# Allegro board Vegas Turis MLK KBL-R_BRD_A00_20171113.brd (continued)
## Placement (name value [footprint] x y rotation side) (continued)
C6317  SC4D7U6D3V3KX-GP  [C603H36]  185.18 65.13 270 bottom
C6318  SC1U10V2KX-1GP  [C402H22]  173.72 57.25 270 top
C6319  SCD1U16V2KX-3GP  [C402H22]  173.81 56.18 270 top
C6320  SC1U10V2KX-1GP  [C402H22]  170.92 70.66 0 bottom
C6401  SCD1U16V2KX-3GP  [C402H22]  195.96 174.23 0 bottom
C6503  SCD1U16V2KX-3GP  [C402H22]  141.15 24.33 270 bottom
C6504  SCD1U16V2KX-3GP  [C402H22]  148.23 17.3 270 bottom
C6701  SCD1U16V2KX-3GP  [C402H22]  180.91 48.43 90 bottom
C6702  SCD1U16V2KX-3GP  [C402H22]  182.55 47.34 270 bottom
C6703  SC10U6D3V3MX-GP  [C603H38]  182.24 52.68 90 bottom
C7601  SCD22U10V2KX-L1-GP  [C402H22]  145.24 132.3 270 top
C7602  SCD22U10V2KX-L1-GP  [C402H22]  145.24 131.41 270 top
C7603  SCD22U10V2KX-L1-GP  [C402H22]  145.24 134.52 270 top
C7604  SCD22U10V2KX-L1-GP  [C402H22]  145.24 133.63 270 top
C7605  SCD22U10V2KX-L1-GP  [C402H22]  143.46 135.91 270 top
C7606  SCD22U10V2KX-L1-GP  [C402H22]  143.46 135.03 270 top
C7607  SCD22U10V2KX-L1-GP  [C402H22]  145.24 136.3 270 top
C7608  SCD22U10V2KX-L1-GP  [C402H22]  145.24 137.18 270 top
C7609  SC47P50V2JN-3GP  [C402H22]  145.9 123.56 0 top
C7710  SCD1U16V2KX-3GP  [C402H22]  156.63 122.39 270 top
C7711  SC1U10V2KX-1GP  [C402H22]  156.63 121.56 270 top
C7713  SC10U6D3V3MX-GP  [C603H38]  156.55 123.95 180 top
C7714  SCD1U16V2KX-3GP  [C402H22]  171.19 125.25 270 top
C7715  SC1U10V2KX-1GP  [C402H22]  171.19 126.14 270 top
C7801  SC1U10V2KX-1GP  [C402H22]  158.19 139.01 270 top
C7802  SC100P50V2JN-3GP  [C402H22]  168.05 171.35 180 bottom
C7803  SC68P50V2JN-1GP  [C402H22]  169.39 172.85 90 bottom
C7805  SC1U10V2KX-1GP  [C402H22]  159.9 139.01 270 top
C7821  SCD1U16V2KX-3GP  [C402H22]  184.3 139.36 180 top
C7822  SCD1U16V2KX-3GP  [C402H22]  179.66 139.64 180 top
C7901  SC6D8P50V2CN-DL-GP  [C402H22]  154.28 123.15 0 bottom
C7903  SC6D8P50V2CN-DL-GP  [C402H22]  154.37 121.46 180 bottom
C7904  SC1U10V2KX-1GP  [C402H22]  169.53 134.61 90 top
C7918  SCD082U16V2KX-GP  [C402H22]  149.26 123.83 180 top
C7919  SCD68U16V3KX-GP-U  [C603H36]  149.12 121.79 270 top
C7920  SCD68U16V3KX-GP-U  [C603H36]  179.3 135.42 0 top
C7921  SCD01U50V2KX-L-GP  [C402H22]  167.52 127.4 0 top
C8001  SC10U6D3V3MX-GP  [C603H38]  194.78 136.24 90 top
C8002  SC10U6D3V3MX-GP  [C603H38]  149.42 125.31 270 top
C8003  SC1U10V2KX-1GP  [C402H22]  166.98 146.83 270 top
C8004  SC1U10V2KX-1GP  [C402H22]  171.38 146.92 90 top
C8005  SC1U10V2KX-1GP  [C402H22]  149.18 150.24 0 top
C8006  SC1U10V2KX-1GP  [C402H22]  173.43 146.9 270 top
C8007  SCD1U16V2KX-3GP  [C402H22]  150.93 150.24 0 top
C8008  SC1U10V2KX-1GP  [C402H22]  170.42 126.99 90 top
C8009  SC1U10V2KX-1GP  [C402H22]  176.88 166.76 180 top
C8010  SC10U6D3V3MX-GP  [C603H38]  167.42 138.63 90 top
C8011  SCD1U16V2KX-3GP  [C402H22]  167.37 137.59 90 top
C8012  SCD1U16V2KX-3GP  [C402H22]  170.68 122.59 0 top
C8013  SC1U10V2KX-1GP  [C402H22]  167.65 139.68 90 top
C8014  SCD01U50V2KX-L-GP  [C402H22]  194.47 138.37 90 top
C8015  SC1U10V2KX-1GP  [C402H22]  163.56 138.3 270 top
C8016  SC10U6D3V3MX-GP  [C603H38]  165.05 137.82 0 top
C8017  SC1U10V2KX-1GP  [C402H22]  170.42 127.83 90 top
C8018  SC1U10V2KX-1GP  [C402H22]  173.61 139.23 0 top
C8019  SC1U10V2KX-1GP  [C402H22]  174.25 122.62 180 bottom
C8020  SC1U10V2KX-1GP  [C402H22]  187.04 123.38 0 bottom
C8021  SC1U10V2KX-1GP  [C402H22]  169.51 139.17 270 top
C8022  SC1U10V2KX-1GP  [C402H22]  169.51 139.99 270 top
C8023  SC1U10V2KX-1GP  [C402H22]  168.22 125.55 90 top
C8024  SC1U10V2KX-1GP  [C402H22]  170.79 135.18 180 top
C8025  SC1U10V2KX-1GP  [C402H22]  168.22 124.74 90 top
C8026  SC1U10V2KX-1GP  [C402H22]  184.68 126.13 90 top
C8027  SC1U10V2KX-1GP  [C402H22]  183 126.13 270 top
C8028  SC1U10V2KX-1GP  [C402H22]  174.23 134.81 90 top
C8029  SC1U10V2KX-1GP  [C402H22]  175.32 137.46 270 top
C8030  SC1U10V2KX-1GP  [C402H22]  177.21 137.85 90 top
C8031  SC1U10V2KX-1GP  [C402H22]  181.28 161.62 180 top
C8032  SC1U10V2KX-1GP  [C402H22]  178.27 147.56 180 top
C8033  SC1U10V2KX-1GP  [C402H22]  179.51 158.91 180 top
C8034  SC1U10V2KX-1GP  [C402H22]  175.35 160.16 180 top
C8035  SC1U10V2KX-1GP  [C402H22]  171.16 138.34 180 top
C8036  SC1U10V2KX-1GP  [C402H22]  175.11 138.7 90 top
C8037  SC1U10V2KX-1GP  [C402H22]  175.37 139.99 90 top
C8038  SC10U6D3V3MX-GP  [C603H38]  168.18 122.37 90 top
C8039  SC10U6D3V3MX-GP  [C603H38]  168.18 121.1 90 top
C8040  SC10U6D3V3MX-GP  [C603H38]  162.86 120.48 90 bottom
C8041  SC10U6D3V3MX-GP  [C603H38]  162.86 123.02 90 bottom
C8042  SC1U10V2KX-1GP  [C402H22]  194.47 137.48 90 top
C8043  SC10U6D3V3MX-GP  [C603H38]  194.66 138.81 270 bottom
C8044  SC10U6D3V3MX-GP  [C603H38]  194.66 137.53 270 bottom
C8045  SC1U10V2KX-1GP  [C402H22]  194.24 136.47 270 bottom
C8046  SCD1U16V2KX-3GP  [C402H22]  169.44 138.35 270 top
C8047  SCD1U16V2KX-3GP  [C402H22]  168.67 136.27 180 top
C8048  SC1U10V2KX-1GP  [C402H22]  167.84 136.34 180 top
C8049  SC1U10V2KX-1GP  [C402H22]  167.01 136.34 180 top
C8050  SC1U10V2KX-1GP  [C402H22]  169.49 136.27 180 top
C8051  SC4D7U6D3V3KX-GP  [C603H36]  162.86 121.75 90 bottom
C8052  SC4D7U6D3V3KX-GP  [C603H36]  168.23 121.82 270 bottom
C8053  SC10U6D3V3MX-GP  [C603H38]  188.83 136.93 270 bottom
C8054  SC1U10V2KX-1GP  [C402H22]  194.67 140.83 90 top
C8055  SC1U10V2KX-1GP  [C402H22]  185.53 137.16 180 bottom
C8056  SCD1U16V2KX-3GP  [C402H22]  186.3 137.16 180 bottom
C8057  SC1U10V2KX-1GP  [C402H22]  163.61 139.95 270 top
C8058  SC1U10V2KX-1GP  [C402H22]  175.32 136.65 270 top
C8059  SC1U10V2KX-1GP  [C402H22]  177.61 136.97 90 top
C8060  SC1U10V2KX-1GP  [C402H22]  172.79 138.33 180 top
C8061  SC1U10V2KX-1GP  [C402H22]  169.51 137.52 270 top
C8062  SC1U10V2KX-1GP  [C402H22]  171.97 138.33 180 top
C8063  SC10U6D3V3MX-GP  [C603H38]  172.8 136.37 270 top
C8064  SC10U6D3V3MX-GP  [C603H38]  168.23 123.09 270 bottom
C8065  SC1U10V2KX-1GP  [C402H22]  163.61 139.13 270 top
C8066  SC22U6D3V3MX-1-GP  [C603H40]  179.66 125.27 180 top
C8101  SC1U10V2KX-1GP  [C402H22]  150.06 166.52 0 top
C8102  SC1U10V2KX-1GP  [C402H22]  188.77 167.27 180 bottom
C8103  SC1U10V2KX-1GP  [C402H22]  150.5 165.13 270 top
C8104  SC1U10V2KX-1GP  [C402H22]  189.32 164.74 180 bottom
C8105  SCD1U16V2KX-3GP  [C402H22]  163.95 161.25 0 top
C8106  SCD1U16V2KX-3GP  [C402H22]  187.74 174.25 0 bottom
C8107  SCD1U16V2KX-3GP  [C402H22]  189.01 170.12 0 bottom
C8108  SCD1U16V2KX-3GP  [C402H22]  186.12 174.26 0 bottom
C8109  SCD1U16V2KX-3GP  [C402H22]  161.03 160.2 90 top
C8110  SCD1U16V2KX-3GP  [C402H22]  153.42 158.22 180 top
C8111  SCD1U16V2KX-3GP  [C402H22]  158.63 162.49 90 top
C8112  SCD1U16V2KX-3GP  [C402H22]  162.54 158.33 180 top
C8113  SC1U10V2KX-1GP  [C402H22]  158.01 174.76 0 bottom
C8114  SC1U10V2KX-1GP  [C402H22]  158.79 174.76 0 bottom
C8115  SC1U10V2KX-1GP  [C402H22]  159.59 174.76 0 bottom
C8116  SC1U10V2KX-1GP  [C402H22]  160.38 174.78 0 bottom
C8117  SC1U10V2KX-1GP  [C402H22]  157.23 174.77 0 bottom
C8118  SC1U10V2KX-1GP  [C402H22]  173.93 174.63 0 bottom
C8119  SC1U10V2KX-1GP  [C402H22]  175.25 174.63 0 bottom
C8120  SC1U10V2KX-1GP  [C402H22]  186.93 174.27 0 bottom
C8121  SC10U6D3V3MX-GP  [C603H38]  179.3 174.66 0 bottom
C8122  SC10U6D3V3MX-GP  [C603H38]  177.07 174.7 0 bottom
C8123  SC1U10V2KX-1GP  [C402H22]  182.96 174.24 0 bottom
C8124  SC1U10V2KX-1GP  [C402H22]  157.58 173.57 180 top
C8125  SC1U10V2KX-1GP  [C402H22]  184.54 174.24 0 bottom
C8126  SC1U10V2KX-1GP  [C402H22]  158.88 173.57 180 top
C8127  SC1U10V2KX-1GP  [C402H22]  160.17 173.57 180 top
C8128  SC1U10V2KX-1GP  [C402H22]  164.12 173.48 180 top
C8129  SC1U10V2KX-1GP  [C402H22]  168.69 173.43 180 top
C8130  SC1U10V2KX-1GP  [C402H22]  190.19 170.31 90 top
C8131  SC10U6D3V3MX-GP  [C603H38]  147.82 156.89 270 top
C8132  SC10U6D3V3MX-GP  [C603H38]  189.92 171.9 90 top
C9106  SC4D7U6D3V3KX-GP  [C603H36]  161.44 60.12 90 bottom
C9107  SCD1U16V2KX-3GP  [C402H22]  153.81 52.85 180 bottom
C9108  SCD1U16V2KX-3GP  [C402H22]  161.53 61.19 90 bottom
C9109  SC4D7U6D3V3KX-GP  [C603H36]  160.77 56.11 270 bottom
C9111  SCD1U16V2KX-3GP  [C402H22]  154.62 52.85 180 bottom
C9112  SCD1U16V2KX-3GP  [C402H22]  160.83 55.05 270 bottom
C9113  SC4D7U6D3V3KX-GP  [C603H36]  150.03 60.55 90 bottom
C9114  SC2200P50V2KX-2GP  [C402H22]  157.65 50.7 270 bottom
C9115  SC2200P50V2KX-2GP  [C402H22]  157.6 51.51 270 bottom
C9116  SCD1U16V2KX-3GP  [C402H22]  157.64 49.92 270 bottom
C9201  SCD1U16V2KX-3GP  [C402H22]  189.04 55.13 90 bottom
C9202  SC1U10V2KX-1GP  [C402H22]  189.04 55.97 90 bottom
CPU1  SKYLAKE-U-GP  [BGA1356M4224-U2H52]  119.5 86.3 0 bottom
D1702  RB751V-40H-GP  [SOD323AKH38]  154.29 62.03 270 top
D2101  BAT54A-11-GP  [SOT-23-9H44]  139.78 43.6 270 bottom
D2102  RB751VM-40TE-17-GP  [SOD323-2513AKH36]  177.71 26.13 270 bottom
D2402  RB751V-40H-GP  [SOD323AKH38]  176.17 45.3 180 bottom
D2403  RB751V-40H-GP  [SOD323AKH38]  176.53 47.91 270 bottom
D2405  RB751V-40H-GP  [SOD323AKH38]  161.02 28.02 0 bottom
D2501  BAT54C-12-GP  [SOT-23-9H44]  38.52 36.54 180 top
D2601  RB551V30-GP  [SOD323AKH38]  108.05 135.91 180 top
D2703  BAT54C-12-GP  [SOT-23-9H44]  173.26 29.49 180 bottom
D2901  BAT54A-11-GP  [SOT-23-9H44]  174.49 13.61 270 bottom
D4001  LBAS16LT1G-GP  [SOT23-2D4-312H44]  66.17 82.45 270 top
D4002  LBAS16LT1G-GP  [SOT23-2D4-312H44]  162.07 80.5 90 bottom
D4304  LBAV99LT1G-1-GP  [SOT23-2D4-312H44]  159.04 181.81 90 top
D4305  LBAV99LT1G-1-GP  [SOT23-2D4-312H44]  161.02 178.23 90 top
D4306  LBAV99LT1G-1-GP  [SOT23-2D4-312H44]  157.82 178.3 90 top
D5502  BAT54C-12-GP  [SOT-23-9H44]  102.46 182 90 top
D5503  BAT54C-12-GP  [SOT-23-9H44]  103.11 176.76 0 top
D5604  RB551V30-GP  [SOD323AKH38]  16.85 81.94 180 top
D5701  LBAW56LT1G-GP  [SOT23-2D4-312H44]  25.61 58.85 0 top
D7601  BAW56-5-GP  [SOT-23-9H44]  146.1 127.87 90 top
D8601  BAT54C-12-GP  [SOT-23-9H44]  140.34 149.91 90 top
D8602  BAT54C-12-GP  [SOT-23-9H44]  190.29 180.48 270 top
DB3  ACES-CON6-58-GP  [50696-00601-001]  156.4 2.3 0 top
DBG1  DM-ACES-CON14-5-GP-01  [DM-87212-1400N-01]  191.45 10.95 270 top
DCIN1  ACES-CON6-63-GP  [50458-00601-W01]  73.4 182.3 180 top
DM1  DDR4-260P-65-GP  [ADDR0206-P013A]  99.4 36.6 0 bottom
DM2  DDR4-260P-64-GP  [ADDR0205-P012A]  91.4 23.4 180 bottom
EC401  SC1KP50V2KX-L-1-GP  [C402H22]  106.71 101.16 0 bottom
EC1702  SC1KP50V2KX-L-1-GP  [C402H22]  144.21 105.54 0 bottom
EC1703  SC1KP50V2KX-L-1-GP  [C402H22]  157.9 76.53 270 bottom
EC1705  SC1KP50V2KX-L-1-GP  [C402H22]  162.86 65.24 0 top
EC1706  SC1KP50V2KX-L-1-GP  [C402H22]  145 105.52 0 bottom
EC1707  SCD1U16V2KX-3GP  [C402H22]  154.31 63.71 270 top
EC1708  SCD01U50V2KX-L-GP  [C402H22]  79.25 83.99 0 top
EC1709  SCD1U16V2KX-3GP  [C402H22]  78.44 89.62 180 top
EC1712  SCD1U16V2KX-3GP  [C402H22]  153.23 67.56 270 bottom
EC1802  SC10P50V2JN-L1-GP  [C402H22]  139.03 62.65 180 bottom
EC1805  SCD1U16V2KX-3GP  [C402H22]  140.02 93.8 180 top
EC1806  SCD1U16V2KX-3GP  [C402H22]  165.29 77.68 90 top
EC1807  SCD1U16V2KX-3GP  [C402H22]  164.1 78.58 270 top
EC1808  SCD1U16V2KX-3GP  [C402H22]  165.04 71.89 90 top
EC1901  SC10P50V2JN-L1-GP  [C402H22]  140.45 52.5 90 bottom
EC1903  SC1KP50V2KX-L-1-GP  [C402H22]  156.63 111.84 90 top
EC2002  SC1KP50V2KX-L-1-GP  [C402H22]  149.6 90.37 180 bottom
EC2101  SCD1U25V2KX-GP  [C402H22]  123.83 87.25 270 top
EC2601  SCD1U16V2KX-3GP  [C402H22]  109.48 135.91 0 top
EC2602  SC10P50V2JN-L1-GP  [C402H22]  108.89 141.02 90 top
EC2701  SCD1U25V2KX-GP  [C402H22]  181.2 12.99 0 top
EC2702  SCD1U25V2KX-GP  [C402H22]  164.34 16.82 270 top
EC2703  SCD1U25V2KX-GP  [C402H22]  184.6 15.2 90 top
EC2704  SCD1U25V2KX-GP  [C402H22]  182.35 12.96 0 top
EC2705  SCD1U25V2KX-GP  [C402H22]  164.17 15.27 270 top
EC2709  SC22P50V2JN-4GP  [C402H22]  169.47 26.92 0 bottom
EC2710  SC22P50V2JN-4GP  [C402H22]  171.12 26.7 0 bottom
EC2711  SC22P50V2JN-4GP  [C402H22]  167.91 26.93 0 bottom
EC2901  SC1KP50V2KX-L-1-GP  [C402H22]  153.59 16.66 270 top
EC2902  SC1KP50V2KX-L-1-GP  [C402H22]  155.28 17.1 270 top
EC2903  SC1KP50V2KX-L-1-GP  [C402H22]  156.98 17.1 270 top
EC2904  SC1KP50V2KX-L-1-GP  [C402H22]  158.68 17.1 270 top
EC2905  SC100P50V2JN-3GP  [C402H22]  180.45 17.93 270 top
EC2906  SC100P50V2JN-3GP  [C402H22]  180.47 18.71 270 top
EC2907  SC100P50V2JN-3GP  [C402H22]  184.53 18.39 180 top
EC2908  SC100P50V2JN-3GP  [C402H22]  183.19 20.75 180 top
EC4301  SC10U25V5KX-L-GP  [C805H56]  76.6 175.09 90 top
EC4302  SCD1U25V2KX-GP  [C402H22]  76.6 173.69 90 top
EC4306  SC10P50V2JN-L1-GP  [C402H22]  148.48 180.21 0 top
EC4307  SCD1U25V2KX-GP  [C402H22]  158.45 177.14 180 bottom
EC4308  SCD1U50V3KX-GP  [C603H36]  157.26 176.79 180 bottom
EC4309  SC10P50V2JN-L1-GP  [C402H22]  153.52 177.78 0 top
EC4310  SC10P50V2JN-L1-GP  [C402H22]  153.49 179.77 180 top
EC5501  SC22P50V2JN-4GP  [C402H22]  105.59 169.92 90 top
EC5502  SC22P50V2JN-4GP  [C402H22]  103.89 169.93 270 top
EC5503  SC33P50V2JN-3GP  [C402H22]  111.34 176.92 90 top
EC5504  SC22P50V2JN-4GP  [C402H22]  106.21 177.05 0 top
EC6401  SCD1U16V2KX-3GP  [C402H22]  186.14 181.61 180 top
EC6402  SCD1U25V2KX-GP  [C402H22]  189.5 13.44 0 bottom
EC6403  SC1KP50V2KX-L-1-GP  [C402H22]  184.92 179.94 270 top
EC6404  SCD1U25V2KX-GP  [C402H22]  170.69 3.46 270 bottom
EC6501  SC33P50V2JN-3GP  [C402H22]  151.38 18.14 270 bottom
EC6502  SC33P50V2JN-3GP  [C402H22]  151.98 22.31 180 top
EC6503  SC33P50V2JN-3GP  [C402H22]  149.69 18.14 90 bottom
EC6504  SC33P50V2JN-3GP  [C402H22]  152.01 20.79 0 top
EC6505  SC33P50V2JN-3GP  [C402H22]  146.42 25.17 270 bottom
EC6506  SC33P50V2JN-3GP  [C402H22]  144.72 25.17 90 bottom
EC8901  SCD1U25V2KX-GP  [C402H22]  109.23 37.19 0 top
EC8902  SCD1U25V2KX-GP  [C402H22]  122.98 78.86 180 top
EC8903  SCD1U25V2KX-GP  [C402H22]  100.13 43.08 180 top
EC8904  SCD1U25V2KX-GP  [C402H22]  112.86 79.22 0 top
EC8905  SCD1U25V2KX-GP  [C402H22]  39.37 17.8 270 bottom
EC8906  SCD1U25V2KX-GP  [C402H22]  42.28 15.62 0 bottom
EC8907  SCD1U25V2KX-GP  [C402H22]  36.25 14.79 90 bottom
EC8908  SCD1U25V2KX-GP  [C402H22]  127.31 81.46 180 top
EC8909  SCD1U25V2KX-GP  [C402H22]  37.32 29.97 90 top
EC8910  SCD1U25V2KX-GP  [C402H22]  83.28 72.82 270 bottom
EC8911  SCD1U25V2KX-GP  [C402H22]  79.92 72.67 0 top
EC8912  SCD1U25V2KX-GP  [C402H22]  93.3 43.39 180 top
EC8913  SCD1U25V2KX-GP  [C402H22]  90.3 17.1 90 top
EC8914  SCD1U25V2KX-GP  [C402H22]  102.57 40.57 180 top
EC8915  SCD1U25V2KX-GP  [C402H22]  62.85 17.93 90 top
EC8916  SCD1U25V2KX-GP  [C402H22]  61.41 181.03 180 top
EC8917  SCD1U25V2KX-GP  [C402H22]  118.23 160.82 90 top
EC8918  SCD1U25V2KX-GP  [C402H22]  194.24 33.24 270 bottom
EC8919  SCD1U25V2KX-GP  [C402H22]  197.94 165.18 0 top
EC8920  SCD1U25V2KX-GP  [C402H22]  171.27 181.76 270 top
EC8921  SCD1U25V2KX-GP  [C402H22]  149.63 35.37 180 top
EC8922  SCD1U25V2KX-GP  [C402H22]  56.58 13.53 270 top
EC8923  SCD1U25V2KX-GP  [C402H22]  138.92 24.42 0 bottom
EC8924  SCD1U25V2KX-GP  [C402H22]  44.7 41.19 270 bottom
EC8925  SCD1U25V2KX-GP  [C402H22]  33.8 52.91 180 bottom
EC8926  SCD1U25V2KX-GP  [C402H22]  135.34 154.27 270 bottom
EC8927  SCD1U25V2KX-GP  [C402H22]  75.4 87.33 270 bottom
EC8928  SCD1U25V2KX-GP  [C402H22]  25.6 41.45 0 bottom
EC9201  SC22P50V2JN-4GP  [C402H22]  183.98 54.7 90 top
EC9202  SC22P50V2JN-4GP  [C402H22]  182.3 54.7 270 top
EC9701  SCD1U25V2KX-GP  [C402H22]  32.14 65.92 270 top
EC9702  SCD1U25V2KX-GP  [C402H22]  99.6 147.4 270 top
EC9703  SCD1U25V2KX-GP  [C402H22]  115.5 155.04 180 top
EC9704  SCD1U25V2KX-GP  [C402H22]  138.23 155.02 0 top
EC9705  SCD1U25V2KX-GP  [C402H22]  176.18 90.37 90 bottom
EC9706  SCD1U25V2KX-GP  [C402H22]  178.18 95.77 0 bottom
EC9707  SCD1U25V2KX-GP  [C402H22]  173.46 92.97 180 bottom
EC9708  SC1KP50V2KX-L-1-GP  [C402H22]  51.64 13.48 0 top
EC9709  SC1KP50V2KX-L-1-GP  [C402H22]  32.1 35.28 270 top
EC9710  SC1KP50V2KX-L-1-GP  [C402H22]  32.2 53.86 270 top
EC9711  SC1KP50V2KX-L-1-GP  [C402H22]  33.64 82.79 270 top
EC9712  SCD1U25V2KX-GP  [C402H22]  151.82 115.32 0 top
EC9713  SCD1U25V2KX-GP  [C402H22]  151.7 115.62 270 bottom
EC9714  SC1KP50V2KX-L-1-GP  [C402H22]  64.16 80.32 90 top
EC9715  SCD1U25V2KX-GP  [C402H22]  190.94 74.88 270 bottom
EC9716  SCD1U25V2KX-GP  [C402H22]  188.86 174.58 270 top
EC9717  SCD1U25V2KX-GP  [C402H22]  64.12 74.88 90 top
EC9718  SCD1U25V2KX-GP  [C402H22]  31.21 51.22 270 bottom
EC9719  SCD1U25V2KX-GP  [C402H22]  28.52 59.32 270 bottom
EC9720  SCD1U25V2KX-GP  [C402H22]  182.62 90.03 180 bottom
EC9721  SCD1U25V2KX-GP  [C402H22]  192.97 47.7 0 top
EC9722  SCD1U25V2KX-GP  [C402H22]  59.62 10.09 270 top
EC9723  SCD1U25V2KX-GP  [C402H22]  22.51 59.01 180 bottom
EC9724  SCD1U25V2KX-GP  [C402H22]  94.61 172.37 90 bottom
EC9725  SC1U10V2KX-1GP  [C402H22]  187.86 162.06 180 top
EC9726  SC1U10V2KX-1GP  [C402H22]  182.62 159.87 0 top
EC9727  SC1U10V2KX-1GP  [C402H22]  182.57 168.56 0 top
EC9728  SC1U10V2KX-1GP  [C402H22]  181.04 169.47 180 top
EC9729  SC1U10V2KX-1GP  [C402H22]  156.79 161.15 180 top
EC9730  SC1U10V2KX-1GP  [C402H22]  150.73 169.49 0 top
EC9731  SC1U10V2KX-1GP  [C402H22]  156.82 168.95 180 top
EC9732  SCD1U25V2KX-GP  [C402H22]  26.56 47.41 180 top
EC9733  SCD1U25V2KX-GP  [C402H22]  58.71 53.53 180 top
EC9734  SCD1U25V2KX-GP  [C402H22]  135.06 42.55 0 top
EC9735  SCD1U25V2KX-GP  [C402H22]  30.55 62.28 180 bottom
EC9736  SCD1U25V2KX-GP  [C402H22]  20.85 72.65 270 bottom
EC9737  SCD1U25V2KX-GP  [C402H22]  60.8 90.72 270 bottom
EC9738  SCD1U25V2KX-GP  [C402H22]  89.75 146.59 90 top
EC9739  SCD1U25V2KX-GP  [C402H22]  182.3 22.51 180 top
EC9740  SC1KP50V2KX-L-1-GP  [C402H22]  62.15 92.99 270 top
EC9741  SCD1U25V2KX-GP  [C402H22]  90.19 183.27 90 top
EC9742  SCD1U25V2KX-GP  [C402H22]  117.64 171.67 90 bottom
EC9743  SCD1U25V2KX-GP  [C402H22]  179.85 13.02 0 top
EC9744  SCD1U25V2KX-GP  [C402H22]  184.61 14.38 90 top
EC9745  SC1KP50V2KX-L-1-GP  [C402H22]  179.74 22.51 180 top
EC9746  SCD1U25V2KX-GP  [C402H22]  187.59 121.85 270 bottom
EC9747  SCD1U25V2KX-GP  [C402H22]  32.76 22.27 270 top
EC9748  SC1KP50V2KX-L-1-GP  [C402H22]  78.47 97 0 top
EC9749  SCD1U25V2KX-GP  [C402H22]  30.98 16.23 90 top
EC9750  SCD1U25V2KX-GP  [C402H22]  184.68 126.94 90 top
EC9751  SCD1U25V2KX-GP  [C402H22]  186.21 123.37 0 bottom
EC9752  SCD1U25V2KX-GP  [C402H22]  183 126.94 270 top
EC9753  SCD1U25V2KX-GP  [C402H22]  166.56 120.63 0 top
ED502  AZ5725-01FDR7G-GP  [SOD882-10D6-1H20]  140.29 49.95 180 bottom
ED1217  AZ5725-01FDR7G-GP  [SOD882-10D6-1H20]  83.54 19.52 180 top
ED1302  AZ5725-01FDR7G-GP  [SOD882-10D6-1H20]  92.08 30.1 45 top
ED3201  TVWDF1004AD0-1-GP  [DFN10G2510H26]  36.16 179.3 270 top
ED3202  TVWDF1004AD0-1-GP  [DFN10G2510H26]  36.16 179.3 270 bottom
ED3602  AZ1045-04F-R7G-GP  [DFN10G2510H26]  18.35 35.14 270 top
ED3603  AZ1045-04F-R7G-GP  [DFN10G2510H26]  18.17 14.92 270 top
ED3604  AZC099-04S-2-GP  [SOT-6H58]  19.69 23.99 90 top
ED3704  AZC099-04S-2-GP  [SOT-6H58]  183.62 29.47 90 bottom
ED5501  AZC099-04S-2-GP  [SOT-6H58]  110.98 173.71 270 top
ED5601  AZ5725-01FDR7G-GP  [SOD882-10D6-1H20]  12.29 78.58 0 top
ED5602  AZ5725-01FDR7G-GP  [SOD882-10D6-1H20]  12.57 72.84 0 top
ED5603  AZ5725-01FDR7G-GP  [SOD882-10D6-1H20]  12.14 75.25 0 top
ED5701  RCLAMP0524P-2-GP  [SLP2510P8-3H26]  15.61 46.46 90 top
ED5702  RCLAMP0524P-2-GP  [SLP2510P8-3H26]  15.64 51.54 90 top
ED5703  RCLAMP0524P-2-GP  [SLP2510P8-3H26]  17.29 55.59 270 top
ED6001  AZ1045-04F-R7G-GP  [DFN10G2510H26]  188.32 41 270 bottom
ED6401  AZ5725-01FDR7G-GP  [SOD882-10D6-1H20]  184.92 179.05 270 top
ED9201  AZC099-04S-2-GP  [SOT-6H58]  188.59 53.01 270 bottom
EL3601  FILTER-4P-137-GP-U  [L125100-4P-4H28]  22.74 24.74 180 top
EL3602  FILTER-4P-137-GP-U  [L125100-4P-4H28]  22.82 22.81 180 top
EL3706  FILTER-4P-137-GP-U  [L125100-4P-4H28]  178.56 33.5 270 top
EL4303  0R0805-PAD-2-GP-U  [0R0805-PAD-1-U]  81.4 174.86 90 top
EL4304  0R0805-PAD-2-GP-U  [0R0805-PAD-1-U]  81.4 176.69 90 top
EL5507  COIL-90OHM-100MHZ-5-GP  [L125100-4P-4H24]  112.1 170.51 0 top
EL5601  BLM18BB470SN1D-GP  [L1608-UH38]  15.04 73.18 270 top
EL5602  BLM18BB470SN1D-GP  [L1608-UH38]  14.72 78.84 270 top
EL5603  BLM18BB470SN1D-GP  [L1608-UH38]  14.6 75.66 270 top
ER5704  0R0402-PAD-2-GP  [0R0402-PAD-1]  18.78 47.7 270 top
ER5705  0R0402-PAD-2-GP  [0R0402-PAD-1]  18.78 46.92 270 top
ER5706  0R0402-PAD-2-GP  [0R0402-PAD-1]  18.83 50.32 270 top
ER5713  0R0402-PAD-2-GP  [0R0402-PAD-1]  18.85 52.05 270 top
ER5714  0R0402-PAD-2-GP  [0R0402-PAD-1]  18.83 51.11 270 top
ER5715  0R0402-PAD-2-GP  [0R0402-PAD-1]  18.85 52.83 270 top
ER5716  0R0402-PAD-2-GP  [0R0402-PAD-1]  18.78 46 270 top
ER5717  0R0402-PAD-2-GP  [0R0402-PAD-1]  18.78 45.21 270 top
EU1701  AZ5325-01FDR7G-GP  [D402H24]  167.69 28.81 180 bottom
F5502  POLYSW-1D1A24V-GP-U  [POLYSW-4633-UH43]  116.67 180.03 0 top
F5503  POLYSW-1D1A24V-GP-U  [POLYSW-4633-UH43]  93.3 180.95 0 top
F5701  POLYSW-1D1A6V-9-GP-U  [POLYSW-2114H30]  14.71 59.87 0 top
FAN1  ETY-CON3-11-GP  [3806K-F03N-04L]  106.4 139.3 90 bottom
FAN261  APL5606AKI-TRG-GP  [SOIC8H69]  94.26 142.21 0 top
FC1901  SC2P50V2CN-GP  [C402H22]  124.98 69.4 90 bottom
FC1902  SC2P50V2CN-GP  [C402H22]  140.57 53.46 270 bottom
FC9702  SC1U10V2KX-1GP  [C402H22]  191.6 38.79 90 top
FC9703  SC1U10V2KX-1GP  [C402H22]  192.51 22 90 top
FC9704  SCD1U25V2KX-GP  [C402H22]  163.08 10.67 90 top
FC9706  SC1U10V2KX-1GP  [C402H22]  99.54 120.87 270 top
FC9707  SC1U10V2KX-1GP  [C402H22]  99.54 119.3 270 top
FC9708  SC1U10V2KX-1GP  [C402H22]  99.54 121.64 270 top
FPR1  HRS-CON6-15-GP  [TF31HM-6S-0D5H-800]  194.95 54.3 270 bottom
G1901  GAP-OPEN  [CON2O-U]  164.01 79.74 90 top
G6401  GAP-OPEN  [CON2O-U]  186.74 178.92 0 top
G6402  GAP-OPEN  [CON2O-U]  186.9 178.69 90 bottom
GPU1  JET-XT-S3-GP  [BGA631M23H82]  171.4 137.3 180 bottom
H1  HOLE335R178-GP  [HOLE335R178]  145.92 73.98 0 top
H2  HOLE335R178-GP  [HOLE335R178]  90.92 73.98 0 top
H3  HOLE335R178-GP  [HOLE335R178]  145.92 99.98 0 top
H4  HOLE335R178-GP  [HOLE335R178]  90.92 99.98 0 top
H5  HOLE335R178-GP  [HOLE335R178]  189.4 130.7 0 top
H6  HOLE335R178-GP  [HOLE335R178]  153.4 130.7 0 top
H7  HOLE335R178-GP  [HOLE335R178]  189.4 143.9 0 top
H8  HOLE335R178-GP  [HOLE335R178]  153.4 143.9 0 top
H9  HOLE335R115-GP  [HOLE335R115]  135.8 143.35 0 bottom
H10  HOLE335R115-GP  [HOLE335R115]  14.4 66.8 0 top
H11  HT85B85X925R29-S-GP  [HT85B85X925R29-S]  21.9 8.3 90 bottom
H12  HOLE335R115-GP  [HOLE335R115]  36.9 169.3 0 top
H13  HOLE335R115-GP  [HOLE335R115]  173.4 84.3 0 top
H14  HT85B85X925R29-S-GP  [HT85B85X925R29-S]  15.4 90.3 270 bottom
H15  HOLE276R91-GP  [HOLE276R91]  143.4 177.8 0 top
H16  HT85BE95R29-U-5-GP  [HT85BE95R29-U-5]  193.9 68.3 90 top
H17  HOLE384X421R115-GP  [HOLE384X421R115]  177.9 4.1 0 bottom
HDA27  ALC3204-CG-GP-U  [QFN40J5-G3D75H36]  172.34 18.73 180 bottom
HDD1  STAR-CON12-1-GP  [132F12-010000-A2-R]  194.4 42.3 270 bottom
HDMI1  SKT-HDMI23-168-GP  [SKT-HDMI23-188137-5]  3.7 51.5 90 bottom
HS1  STF237R128H128-3-GP  [STF237R128H128]  120.65 157.3 180 bottom
IOBD1  ACES-CON30-9-GP-U2  [51519-03001-W02-U2]  195.4 22.3 270 bottom
KB1  PTWO-CON30-10-GP  [196370-30041-3]  187.05 110.08 270 top
KBC24  MEC1416-NU-D0-GP  [TQFP128-2H48]  165.06 39.73 180 bottom
L3101  IND-4D7UH-242-GP  [L2520-D820H41]  52.86 180.37 180 top
L8001  MMZ1005S241C-GP  [L402H22]  194.63 139.16 270 top
L8002  BLM15AG121SN-1GP  [L402H22]  194.67 139.99 270 top
L8003  BLM15AG121SN-1GP  [L402H22]  187.08 137.07 0 bottom
LCD1  IPEX-CON40-3-GP  [20455-040E-12]  104.4 179.3 0 bottom
LED1  LED-YW-5-GP  [LED3020-3P-19H44]  169.4 1.8 90 bottom
LOM31  RTL8111G-CGT-1-GP-U2  [QFN32J4-G2D85H36]  48.55 174.68 90 top
NOREF  -  []  67.08 -440.4 0 top
NOREF#2  *  [unnamed#2]  58.43 183.09 0 top
NOREF#3  -  []  -43.06 -116.53 0 top
NOREF#4  -  [unnamed#2]  7.9 64.3 90 top
NOREF#5  -  []  -43.06 -116.53 0 top
NOREF#6  -  [unnamed#2]  26.76 108.08 0 top
NOREF#7  -  []  117.33 55 0 top
NOREF#8  -  []  -33.42 -540.54 0 top
NOREF#9  -  []  -108.68 -139.45 0 top
NOREF#10  -  []  169.4 225.3 0 top
NOREF#11  -  [unnamed#2]  -5.75 188.07 0 top
NOREF#12  *  [unnamed#2]  26.52 22.18 0 top
NOREF#13  -  []  -147.2 -182.79 0 top
NOREF#14  -  []  -405.78 -323.33 0 top
NOREF#15  -  [unnamed#2]  138.47 190.94 0 top
NOREF#16  -  []  -47.01 -100.72 0 top
NOREF#17  *  [unnamed#2]  198.39 2.04 0 top
NOREF#18  -  [unnamed#2]  -5.65 1.79 0 top
NOREF#19  -  []  -77.08 -107.55 0 top
NOREF#20  -  [unnamed#2]  172.9 185.3 0 top
NOREF#21  -  []  205.35 79.08 0 top
NOREF#22  -  []  -39.47 -105.43 0 top
NOREF#23  -  []  -46.65 -1.45 0 top
NOREF#24  -  []  -231.06 -69.96 0 top
NOREF#25  -  []  -47.01 -100.72 0 top
NOREF#26  -  []  72.02 65.94 0 top
NOREF#27  -  []  -173.68 -122.6 0 top
NOREF#28  -  []  -184.51 -169.98 0 top
NOREF#29  *  [unnamed#2]  196.34 180.09 0 top
NOREF#30  -  []  -194.9 -73.99 0 top
NOREF#31  -  []  25.45 -516.55 0 top
NOREF#32  -  []  -178.5 -152.69 0 top
NOREF#33  -  []  -196.29 -98.98 0 top
NOREF#34  -  []  -142.38 -535.5 0 top
NOREF#35  -  [unnamed#2]  202.32 3.69 0 top
NOREF#36  -  []  -39.47 -105.43 0 top
NOREF#37  *  [unnamed#2]  -1.62 3.48 0 top
NOREF#38  *  [unnamed#2]  -1.87 161.72 0 top
NOREF#39  -  [unnamed#2]  202.49 143.16 0 top
NOREF#40  *  [unnamed#2]  -1.62 3.48 180 bottom
NOREF#41  *  [unnamed#2]  132.73 67.39 180 bottom
NOREF#42  -  []  116.26 66.03 180 bottom
NOREF#43  *  [unnamed#2]  198.39 2.04 180 bottom
NOREF#44  *  [unnamed#2]  85.51 96.49 180 bottom
NOREF#45  -  []  506.87 -100.72 180 bottom
NOREF#46  *  [unnamed#2]  -1.87 161.72 180 bottom
NOREF#47  -  []  510.58 -116.53 180 bottom
NOREF#48  *  [unnamed#2]  21.81 23.23 180 bottom
NOREF#49  -  []  502.56 -105.43 180 bottom
NOREF#50  -  []  502.56 -105.43 180 bottom
NOREF#51  -  []  65.67 67.74 180 bottom
NOREF#52  *  [unnamed#2]  179.64 179.02 180 bottom
NOREF#53  *  [unnamed#2]  58.43 183.09 180 bottom
NOREF#54  -  []  510.58 -116.53 180 bottom
NOREF#55  -  []  506.87 -100.72 180 bottom
ODD1  ACES-CON20-30-GP-U1  [51519-02001-W03-U1]  190.4 84.8 90 top
PC1001  SC22U6D3V3MX-1-GP  [C603H40]  125 108.69 270 top
PC1002  SC22U6D3V3MX-1-GP  [C603H40]  119.7 89.56 90 top
PC1003  SC22U6D3V3MX-1-GP  [C603H40]  128.42 117.17 270 bottom
PC1004  SC22U6D3V3MX-1-GP  [C603H40]  127.98 110.23 90 top
PC1005  SC22U6D3V3MX-1-GP  [C603H40]  127.98 111.5 90 top
PC1006  SC22U6D3V3MX-1-GP  [C603H40]  127.98 108.96 90 top
PC1007  SC22U6D3V3MX-1-GP  [C603H40]  127.98 112.78 90 top
PC1008  SC22U6D3V3MX-1-GP  [C603H40]  125.31 107.67 180 bottom
PC1009  SC22U6D3V3MX-1-GP  [C603H40]  115.73 88.01 270 top
PC1010  SC22U6D3V3MX-1-GP  [C603H40]  112.58 109.16 270 top
PC1011  SC22U6D3V3MX-1-GP  [C603H40]  111.62 114.35 270 top
PC1012  SC22U6D3V3MX-1-GP  [C603H40]  127.98 116.59 90 top
PC1013  SC22U6D3V3MX-1-GP  [C603H40]  119.7 84.45 90 top
PC1014  SC22U6D3V3MX-1-GP  [C603H40]  115.73 86.72 270 top
PC1015  SC22U6D3V3MX-1-GP  [C603H40]  128.42 115.88 270 bottom
PC1016  SC22U6D3V3MX-1-GP  [C603H40]  112.58 107.88 270 top
PC1017  SC22U6D3V3MX-1-GP  [C603H40]  119.7 88.28 90 top
PC1018  SC22U6D3V3MX-1-GP  [C603H40]  127.98 107.69 90 top
PC1019  SC22U6D3V3MX-1-GP  [C603H40]  119.7 85.72 90 top
PC1020  SC22U6D3V3MX-1-GP  [C603H40]  115.73 89.31 270 top
PC1021  SC22U6D3V3MX-1-GP  [C603H40]  119.69 90.85 90 top
PC1022  SC22U6D3V3MX-1-GP  [C603H40]  125 110.03 270 top
PC1023  SC22U6D3V3MX-1-GP  [C603H40]  126.65 107.67 180 bottom
PC1024  SC22U6D3V3MX-1-GP  [C603H40]  119.7 87 90 top
PC1025  SC22U6D3V3MX-1-GP  [C603H40]  111.62 115.62 270 top
PC1026  SC22U6D3V3MX-1-GP  [C603H40]  127.98 114.05 90 top
PC1027  SC22U6D3V3MX-1-GP  [C603H40]  127.98 115.32 90 top
PC1028  SC22U6D3V3MX-1-GP  [C603H40]  121.72 92.97 90 top
PC1029  SC22U6D3V3MX-1-GP  [C603H40]  120.25 81.54 270 top
PC1030  SC22U6D3V3MX-1-GP  [C603H40]  117.84 95.02 270 top
PC1031  SC22U6D3V3MX-1-GP  [C603H40]  97.75 86.59 270 top
PC1032  SC22U6D3V3MX-1-GP  [C603H40]  99.65 114.26 270 top
PC1033  SC22U6D3V3MX-1-GP  [C603H40]  108.62 108.08 270 bottom
PC1034  SC22U6D3V3MX-1-GP  [C603H40]  97.74 89.18 270 top
PC1035  SC22U6D3V3MX-1-GP  [C603H40]  159.67 81.25 0 top
PC1036  SC22U6D3V3MX-1-GP  [C603H40]  160.96 81.25 0 top
PC1037  SC22U6D3V3MX-1-GP  [C603H40]  162.25 81.23 0 top
PC1038  SC22U6D3V3MX-1-DL-GP  [C603H40]  165.17 83.76 180 bottom
PC1039  SC22U6D3V3MX-1-DL-GP  [C603H40]  166.98 83.77 180 bottom
PC1040  SC22U6D3V3MX-1-GP  [C603H40]  111.64 116.93 270 top
PC1041  SC22U6D3V3MX-1-GP  [C603H40]  107.99 114.13 90 top
PC1042  SC22U6D3V3MX-1-GP  [C603H40]  108 107.65 90 top
PC1043  SC22U6D3V3MX-1-GP  [C603H40]  107.93 84.13 0 top
PC1044  SC22U6D3V3MX-1-GP  [C603H40]  104.96 88.62 0 top
PC1045  SC22U6D3V3MX-1-GP  [C603H40]  134.3 114.68 270 top
PC1046  SC22U6D3V3MX-1-GP  [C603H40]  139.21 111.76 270 bottom
PC1047  SC22U6D3V3MX-1-GP  [C603H40]  124 84.32 180 top
PC1048  SC22U6D3V3MX-1-GP  [C603H40]  139.21 113.03 270 bottom
PC1049  SC22U6D3V3MX-1-GP  [C603H40]  123.07 89.36 0 top
PC1050  SC22U6D3V3MX-1-GP  [C603H40]  133.18 110.64 90 bottom
PC1051  SC22U6D3V3MX-1-GP  [C603H40]  133.18 111.91 90 bottom
PC1052  SC22U6D3V3MX-1-GP  [C603H40]  139.21 113.06 90 top
PC1053  SC22U6D3V3MX-1-GP  [C603H40]  104.66 85.3 0 top
PC1054  SC22U6D3V3MX-1-GP  [C603H40]  122.84 91.19 270 top
PC1055  SC10U6D3V3MX-GP  [C603H38]  61.09 35.26 90 top
PC1056  SC4D7P50V2BN-GP  [C402H22]  125.97 78.44 270 top
PC1057  SC10U6D3V3MX-GP  [C603H38]  61.12 36.58 90 top
PC1058  SC10U6D3V3MX-GP  [C603H38]  59.72 19.48 180 top
PC1059  SC4D7P50V2BN-GP  [C402H22]  62.85 17.15 90 top
PC1060  SC4D7P50V2BN-GP  [C402H22]  101.48 22.51 180 top
PC1061  SC4D7P50V2BN-GP  [C402H22]  91.06 29.09 45 top
PC1062  SC22U6D3V3MX-1-GP  [C603H40]  69.94 30.7 45 top
PC1063  SC22U6D3V3MX-1-GP  [C603H40]  84.21 40.62 0 top
PC1064  SC22U6D3V3MX-1-GP  [C603H40]  61.37 33.68 90 top
PC1065  SC22U6D3V3MX-1-GP  [C603H40]  105.95 85.3 0 top
PC1066  SC22U6D3V3MX-1-GP  [C603H40]  128.41 114.6 270 bottom
PC1067  SC22U6D3V3MX-1-GP  [C603H40]  111.62 111.74 270 top
PC1068  SC22U6D3V3MX-1-GP  [C603H40]  111.63 113.04 270 top
PC1069  SC22U6D3V3MX-1-GP  [C603H40]  99.65 109.17 270 top
PC1070  SC22U6D3V3MX-1-GP  [C603H40]  97.74 90.46 270 top
PC1071  SC22U6D3V3MX-1-GP  [C603H40]  99.65 116.8 270 top
PC1072  SC22U6D3V3MX-1-GP  [C603H40]  99.65 115.53 270 top
PC1073  SC22U6D3V3MX-1-GP  [C603H40]  108 110.24 90 top
PC1074  SC22U6D3V3MX-1-GP  [C603H40]  99.65 112.98 270 top
PC1075  SC22U6D3V3MX-1-GP  [C603H40]  99.65 110.44 270 top
PC1076  SC22U6D3V3MX-1-GP  [C603H40]  97.75 87.89 270 top
PC1077  SC22U6D3V3MX-1-GP  [C603H40]  113.9 84.94 180 top
PC1078  SC22U6D3V3MX-1-GP  [C603H40]  107.99 116.73 90 top
PC1079  SC22U6D3V3MX-1-GP  [C603H40]  97.74 91.75 270 top
PC1080  SC22U6D3V3MX-1-GP  [C603H40]  99.65 118.07 270 top
PC1081  SC22U6D3V3MX-1-GP  [C603H40]  107.99 115.46 90 top
PC1082  SC22U6D3V3MX-1-GP  [C603H40]  102.04 109.93 180 bottom
PC1083  SC22U6D3V3MX-1-GP  [C603H40]  99.65 111.71 270 top
PC1084  SC22U6D3V3MX-1-GP  [C603H40]  99.65 107.89 270 top
PC1085  SC22U6D3V3MX-1-GP  [C603H40]  103.33 109.93 180 bottom
PC1086  SC22U6D3V3MX-1-GP  [C603H40]  108 108.97 90 top
PC1087  SC22U6D3V3MX-1-GP  [C603H40]  97.74 94.32 270 top
PC1088  SC22U6D3V3MX-1-GP  [C603H40]  100.39 93.6 180 top
PC1089  SC22U6D3V3MX-1-GP  [C603H40]  110.78 86.82 90 top
PC1090  SC22U6D3V3MX-1-GP  [C603H40]  97.74 93.04 270 top
PC1091  SC22U6D3V3MX-1-GP  [C603H40]  110.78 85.52 90 top
PC1092  SC22U6D3V3MX-1-GP  [C603H40]  110.78 88.11 90 top
PC1093  SC22U6D3V3MX-1-GP  [C603H40]  108 112.81 90 top
PC1094  SC22U6D3V3MX-1-GP  [C603H40]  108 111.51 90 top
PC1095  SC22U6D3V3MX-1-GP  [C603H40]  110.78 89.41 90 top
PC1096  SC22U6D3V3MX-1-GP  [C603H40]  112.61 84.94 180 top
PC1097  SC22U6D3V3MX-1-GP  [C603H40]  120.3 95.02 90 top
PC1098  SC22U6D3V3MX-1-GP  [C603H40]  124.37 89.36 0 top
PC1099  SC22U6D3V3MX-1-GP  [C603H40]  115.73 85.42 270 top
PC1105  SC22U6D3V3MX-1-GP  [C603H40]  129.2 85.94 180 top
PC1106  SC22U6D3V3MX-1-GP  [C603H40]  123.68 86.18 270 top
PC4301  SC1U50V3KX-GP  [C603H32]  81.62 167.65 0 top
PC4302  SCD1U50V3KX-GP  [C603H36]  84.46 172.21 180 top
PC4303  SCD01U50V2KX-L-GP  [C402H22]  85.56 172.71 180 top
PC4304  SCD01U50V2KX-L-GP  [C402H22]  86.38 172.71 180 top
PC4305  SCD01U50V2KX-L-GP  [C402H22]  87.19 172.71 180 top
PC4306  SC10U25V5KX-L-GP  [C805H56]  88.52 172.53 180 top
PC4401  SC10U25V5KX-L-GP  [C805H56]  169.27 178.77 90 top
PC4402  SC2K2P50V2KX-L-GP  [C402H22]  139.35 182.13 270 bottom
PC4403  SC2K2P50V2KX-L-GP  [C402H22]  139.35 181.31 270 bottom
PC4404  SC2K2P50V2KX-L-GP  [C402H22]  134.93 178.87 0 top
PC4405  SCD022U25V2KX-DLGP  [C402H22]  136.77 180.14 270 top
PC4406  SC470P50V2KX-L-GP  [C402H22]  136.78 179.3 270 top
PC4407  SC1KP50V2KX-L-1-GP  [C402H22]  129.45 174.98 0 bottom
PC4408  SC1KP50V2KX-L-1-GP  [C402H22]  130.8 175.43 90 top
PC4409  SC1KP50V2KX-L-1-GP  [C402H22]  128.09 176.17 90 bottom
PC4410  SC10U25V5KX-L-GP  [C805H56]  152.15 173.66 270 bottom
PC4418  SC10U25V5KX-L-GP  [C805H56]  128.43 165.31 180 top
PC4419  SCD01U50V2KX-L-GP  [C402H22]  131.48 180.64 90 bottom
PC4427  SC10U25V5KX-L-GP  [C805H56]  126.59 165.32 0 bottom
PC4431  SCD22U25V3KX-GP  [C603H40]  132.41 171.62 0 bottom
PC4433  SCD47U25V3KX-1GP  [C603H36]  127.9 182.42 270 top
PC4435  SC1U50V3KX-GP  [C603H32]  133.98 174.74 270 top
PC4436  SC10P50V2JN-L1-GP  [C402H22]  136.19 175.81 270 top
PC4438  SC10U25V5KX-L-GP  [C805H56]  126.59 165.32 180 top
PC4439  SC1U10V2KX-1GP  [C402H22]  126.25 177.47 270 top
PC4445  SC1U10V2KX-1GP  [C402H22]  134.9 172.01 270 bottom
PC4446  SC1U10V2KX-1GP  [C402H22]  136.59 172.01 90 bottom
PC4452  SC10U25V5KX-L-GP  [C805H56]  146.55 170.07 180 bottom
PC4453  SC10U25V5KX-L-GP  [C805H56]  148.48 177.55 0 bottom
PC4456  SCD1U25V2KX-GP  [C402H22]  124.72 165.1 180 top
PC4459  SC10U25V5KX-L-GP  [C805H56]  128.43 165.31 0 bottom
PC4461  SC2K2P50V2KX-L-GP  [C402H22]  137.64 175.19 270 bottom
PC4462  SC2K2P50V2KX-L-GP  [C402H22]  139.33 175.19 90 bottom
PC4463  SCD1U25V2KX-GP  [C402H22]  138.91 174.37 270 bottom
PC4464  SCD1U25V2KX-GP  [C402H22]  149.79 177.38 0 bottom
PC4466  SCD1U25V2KX-GP  [C402H22]  129.39 179.15 180 bottom
PC4467  SC2K2P50V2KX-L-GP  [C402H22]  130.22 179.94 0 bottom
PC4468  SC2K2P50V2KX-L-GP  [C402H22]  130.22 178.26 180 bottom
PC4471  SCD22U10V2KX-L1-GP  [C402H22]  121.05 178.11 270 top
PC4509  SC4D7U25V5KX-L2-GP  [C805H58]  41.99 68.92 90 top
PC4516  SCD1U50V3KX-GP  [C603H36]  53.64 74.75 270 top
PC4517  SCD1U16V2KX-3GP  [C402H22]  38.2 47.51 90 bottom
PC4518  SCD1U16V2KX-3GP  [C402H22]  56.42 54.24 270 bottom
PC4519  SC10U25V5KX-L-GP  [C805H56]  46.18 70.68 270 top
PC4520  SC330P50V2KX-3GP  [C402H22]  48.05 68.02 90 bottom
PC4522  SC18P50V2JN-1-GP  [C402H22]  49.71 78.63 270 top
PC4523  SC18P50V2JN-1-GP  [C402H22]  45.29 79.8 0 top
PC4524  SC1U50V3KX-GP  [C603H32]  49.17 70.48 0 top
PC4525  SCD1U50V3KX-GP  [C603H36]  41.96 67.38 90 top
PC4526  SC4D7U6D3V3KX-GP  [C603H36]  48.47 79.18 90 bottom
PC4527  SC10U25V5KX-L-GP  [C805H56]  54.69 69.05 270 top
PC4528  SC10U25V5KX-L-GP  [C805H56]  41.99 70.73 90 top
PC4529  SC4D7U25V5KX-L2-GP  [C805H58]  54.67 70.98 270 top
PC4530  SCD1U50V3KX-GP  [C603H36]  54.67 67.44 270 top
PC4531  SCD01U50V2KX-L-GP  [C402H22]  48.08 70.81 0 top
PC4535  SCD1U50V3KX-GP  [C603H36]  43.48 74.24 90 top
PC4536  SC560P50V-GP  [C603]  56.59 66.96 90 bottom
PC4601  SC2200P50V2KX-2DLGP  [C402H22]  115.11 139.32 0 bottom
PC4602  SCD1U25V2KX-GP  [C402H22]  127.56 149.61 0 top
PC4603  SCD1U25V2KX-GP  [C402H22]  115.72 146.5 270 top
PC4604  SC330P50V2KX-3-DL-GP  [C402H22]  127.01 143.43 90 bottom
PC4605  SCD068U25V2KX-GP  [C402H22]  117.33 143.81 90 top
PC4606  SCD22U25V3KX-GP  [C603H40]  118.83 148.07 180 top
PC4607  SC1U10V2KX-1GP  [C402H22]  121.62 144.76 0 top
PC4608  SCD033U25V2KX-GP  [C402H22]  114.08 146.53 270 top
PC4609  SCD01U50V2KX-L-GP  [C402H22]  127.74 138.47 90 top
PC4610  SC33P50V2JN-3GP  [C402H22]  123.94 143.57 90 top
PC4611  SC2K2P50V2KX-L-GP  [C402H22]  117.61 145.5 270 top
PC4612  SC2K2P50V2KX-L-GP  [C402H22]  129.48 143.52 270 bottom
PC4613  SCD01U50V2KX-L-GP  [C402H22]  116.88 142.63 0 top
PC4614  SC330P50V2KX-3GP  [C402H22]  129.33 140.17 270 bottom
PC4615  SCD01U50V2KX-L-GP  [C402H22]  130.13 142.68 90 top
PC4616  SC1KP50V2KX-L-1-GP  [C402H22]  116.07 142.66 0 top
PC4617  SC1KP50V2KX-L-1-GP  [C402H22]  115.02 142.61 180 bottom
PC4618  SC1KP50V2KX-L-1-GP  [C402H22]  129.71 142.33 180 bottom
PC4619  SC1KP50V2KX-L-1-GP  [C402H22]  127 141.86 270 top
PC4620  SCD01U50V2KX-L-GP  [C402H22]  114.75 140.57 270 top
PC4621  SC680P50V2KX-2GP  [C402H22]  113.75 140.71 270 bottom
PC4622  SCD01U50V2KX-L-GP  [C402H22]  123.91 141.99 270 top
PC4623  SC2K2P50V2KX-L-GP  [C402H22]  130.44 139.39 0 top
PC4624  SC33P50V2JN-3GP  [C402H22]  116.43 139.77 90 bottom
PC4625  SCD022U25V2KX-DLGP  [C402H22]  126.93 137.69 90 top
PC4626  SCD022U25V2KX-DLGP  [C402H22]  123.83 138.05 270 top
PC4628  SCD033U25V2KX-GP  [C402H22]  127.72 139.25 90 top
PC4629  SC330P50V2KX-3-DL-GP  [C402H22]  119.97 142.7 270 top
PC4630  SCD1U25V2KX-GP  [C402H22]  123.9 140.41 270 top
PC4631  SCD1U25V2KX-GP  [C402H22]  114.48 139.06 180 top
PC4632  SC2K2P50V2KX-L-GP  [C402H22]  116.05 139.34 0 top
PC4633  SCD1U25V2KX-GP  [C402H22]  129.4 138.06 90 top
PC4634  SCD1U25V2KX-GP  [C402H22]  113.31 137.83 270 top
PC4635  SCD022U25V2KX-DLGP  [C402H22]  113.31 139.42 270 top
PC4637  SCD01U50V2KX-L-GP  [C402H22]  120.98 140.54 180 top
PC4638  SC330P50V2KX-3-DL-GP  [C402H22]  121.77 140.54 180 top
PC4639  SC33P50V2JN-3GP  [C402H22]  121.4 135.98 90 top
PC4640  SC4700P50V2KX-1DLGP  [C402H22]  120.54 134.4 270 top
PC4641  SC330P50V2KX-3-DL-GP  [C402H22]  120.23 135.59 0 top
PC4642  SC1KP50V2KX-L-1-GP  [C402H22]  117.82 136.59 0 top
PC4643  SC1KP50V2KX-L-1-GP  [C402H22]  119.02 136 90 top
PC4644  SCD01U50V2KX-L-GP  [C402H22]  117.72 134.65 0 top
PC4651  SC1KP50V2KX-L-1-GP  [C402H22]  129.5 144.3 270 bottom
PC4652  SCD022U25V2KX-DLGP  [C402H22]  113.32 138.62 270 top
PC4653  SCD047U25V2KX-GP  [C402H22]  127.72 140.02 90 top
PC4661  SC470P50V2KX-3GP  [C402H22]  129.32 139.39 270 bottom
PC4662  SC220P50V2KX-3GP  [C402H22]  130.5 142.33 180 bottom
PC4701  SC10U25V5KX-L-GP  [C805H56]  100.72 125.99 180 bottom
PC4702  SC10U25V5KX-L-GP  [C805H56]  98.86 125.99 180 bottom
PC4703  SC10U25V5KX-L-GP  [C805H56]  98.86 125.99 0 top
PC4704  SC10U25V5KX-L-GP  [C805H56]  100.72 125.99 0 top
PC4706  SC1KP50V2KX-L-1-GP  [C402H22]  99.33 123.61 270 bottom
PC4707  SCD22U25V3KX-GP  [C603H40]  104.66 130.05 180 bottom
PC4708  SC1U10V2KX-1GP  [C402H22]  105.52 123.07 90 bottom
PC4802  SC10U25V5KX-L-GP  [C805H56]  119.15 125.96 0 top
PC4803  SC10U25V5KX-L-GP  [C805H56]  117.29 125.97 180 bottom
PC4804  SC10U25V5KX-L-GP  [C805H56]  119.15 125.97 180 bottom
PC4805  SC10U25V5KX-L-GP  [C805H56]  117.29 125.96 0 top
PC4808  SCD22U25V3KX-GP  [C603H40]  122.77 129.87 180 bottom
PC4809  SC1U10V2KX-1GP  [C402H22]  124.06 122.74 90 bottom
PC4810  SC1KP50V2KX-L-1-GP  [C402H22]  118.97 123.76 0 bottom
PC4811  SCD22U25V3KX-GP  [C603H40]  113.76 129.93 180 bottom
PC4812  SC1U10V2KX-1GP  [C402H22]  114.92 122.94 90 bottom
PC4813  SC1KP50V2KX-L-1-GP  [C402H22]  109.45 123.5 0 bottom
PC4814  SC10U25V5KX-L-GP  [C805H56]  108.28 126.3 180 bottom
PC4815  SC10U25V5KX-L-GP  [C805H56]  110.11 126.3 180 bottom
PC4816  SC10U25V5KX-L-GP  [C805H56]  108.18 126.07 0 top
PC4817  SC10U25V5KX-L-GP  [C805H56]  110.03 126.07 0 top
PC5001  SC2D2U10V3KX-L-GP  [C603H36]  120.13 148.07 180 top
PC5002  SC10U25V5KX-L-GP  [C805H56]  135.2 125.45 90 top
PC5003  SC10U25V5KX-L-GP  [C805H56]  135.21 123.62 90 top
PC5004  SCD1U25V2KX-GP  [C402H22]  134.94 127.57 90 top
PC5005  SCD22U25V3KX-GP  [C603H40]  132.23 132.82 0 top
PC5102  SC1U10V2KX-1GP  [C402H22]  42.13 20.89 0 top
PC5103  SC4D7U25V5KX-L2-GP  [C805H58]  48.37 17.91 90 bottom
PC5104  SC4D7U25V5KX-L2-GP  [C805H58]  48.37 19.72 90 bottom
PC5105  SCD1U25V2KX-GP  [C402H22]  48.37 21.04 90 bottom
PC5106  SCD1U16V2KX-3GP  [C402H22]  40.15 18.37 0 top
PC5107  SC1U10V2KX-1GP  [C402H22]  43.28 22.4 90 top
PC5108  SCD1U50V3KX-GP  [C603H36]  40.66 27.45 0 top
PC5109  SC10U6D3V3MX-GP  [C603H38]  38.07 27.45 180 top
PC5110  SC22U6D3V3MX-1-DL-GP  [C603H40]  53.44 32.95 180 bottom
PC5111  SC22U6D3V3MX-1-DL-GP  [C603H40]  53.46 31.68 0 top
PC5112  SC22U6D3V3MX-1-DL-GP  [C603H40]  57.11 31.69 0 top
PC5113  SC22U6D3V3MX-1-DL-GP  [C603H40]  55.31 32.97 180 bottom
PC5114  SC22U6D3V3MX-1-DL-GP  [C603H40]  55.3 31.69 0 top
PC5115  SC18P50V2JN-1-GP  [C402H22]  35.47 18.5 90 top
PC5116  SCD047U25V2KX-GP  [C402H22]  37.66 19.54 180 bottom
PC5117  SC10U6D3V3MX-GP  [C603H38]  35.87 23.02 0 top
PC5118  SC10U6D3V3MX-GP  [C603H38]  34.59 23.02 0 top
PC5120  SC2200P50V2KX-2GP  [C402H22]  46.93 22.52 0 top
PC5152  SC10U6D3V3MX-GP  [C603H38]  139.17 19.01 180 bottom
PC5153  SC68P50V2JN-1GP  [C402H22]  135.62 28.35 90 bottom
PC5154  SC22U6D3V3MX-1-DL-GP  [C603H40]  138.34 28.92 270 bottom
PC5155  SC4700P50V2KX-1GP  [C402H22]  130.36 18.1 180 bottom
PC5156  SC1U50V3KX-GP  [C603H32]  137.17 17.4 270 bottom
PC5301  SC22U6D3V3MX-1-DL-GP  [C603H40]  171.53 71.05 0 top
PC5302  SC4D7U25V5KX-L2-GP  [C805H58]  181.59 79.74 0 bottom
PC5303  SC22U6D3V3MX-1-DL-GP  [C603H40]  169.87 77.41 180 top
PC5304  SCD1U25V2KX-GP  [C402H22]  178.88 78.14 0 bottom
PC5305  SC22U6D3V3MX-1-DL-GP  [C603H40]  173.37 71.05 0 top
PC5306  SC22U6D3V3MX-1-DL-GP  [C603H40]  171.68 77.41 180 top
PC5307  SC22U6D3V3MX-1-DL-GP  [C603H40]  169.68 71.05 0 top
PC5308  SCD1U25V2KX-GP  [C402H22]  180.83 72.11 90 bottom
PC5309  SC10U25V5KX-L-GP  [C805H56]  181.26 70.73 90 bottom
PC5310  SC10U25V5KX-L-GP  [C805H56]  180.83 70.82 270 top
PC5312  SC220P50V2KX-3GP  [C402H22]  186.24 74.23 0 bottom
PC5313  SCD01U50V2KX-L-GP  [C402H22]  182.87 79.48 0 bottom
PC5314  SC1KP50V2KX-L-1-GP  [C402H22]  185.77 76.43 270 bottom
PC5315  SC2200P50V2KX-2GP  [C402H22]  178.15 70.99 270 bottom
PC5401  SC1U10V2KX-1GP  [C402H22]  161.97 61.85 270 top
PC5402  SC22U6D3V3MX-1-DL-GP  [C603H40]  166.4 72.48 270 bottom
PC5403  SC10U6D3V3MX-GP  [C603H38]  165.49 63.25 180 bottom
PC5404  SC22U6D3V3MX-1-DL-GP  [C603H40]  166.38 70.64 270 bottom
PC5405  SC68P50V2JN-1GP  [C402H22]  161.44 72.57 90 bottom
PC5406  SC4700P50V2KX-1GP  [C402H22]  161.46 64.03 90 top
PC8501  SCD01U50V2KX-L-GP  [C402H22]  163.34 111.87 0 top
PC8502  SCD1U25V2KX-1-DL-GP  [C402H22]  153.78 110.97 0 top
PC8503  SC1KP50V2KX-L-1-GP  [C402H22]  159.4 109.81 270 top
PC8506  SC330P50V2KX-3GP  [C402H22]  173.76 108 270 top
PC8507  SCD22U25V3KX-GP  [C603H40]  167.37 105.41 0 bottom
PC8508  SC1U10V2KX-1GP  [C402H22]  163.88 108.35 270 top
PC8509  SC1U10V2KX-1GP  [C402H22]  168.33 108.48 270 bottom
PC8510  SCD22U25V3KX-GP  [C603H40]  167.37 110.66 90 bottom
PC8511  SC1KP50V2KX-L-1-GP  [C402H22]  157.32 113.35 180 bottom
PC8512  SC100P50V2JN-3GP  [C402H22]  164.2 111.86 0 top
PC8513  SC1KP50V2KX-L-1-GP  [C402H22]  162.07 113.99 90 bottom
PC8514  SC180P50V2JN-1GP  [C402H22]  163.79 113.92 270 bottom
PC8515  SC330P50V2KX-3GP  [C402H22]  164.3 116.08 180 bottom
PC8516  SC330P50V2KX-3GP  [C402H22]  165.13 116.92 180 bottom
PC8517  SCD22U10V2KX-L1-GP  [C402H22]  159.99 114.58 180 top
PC8518  SCD22U10V2KX-L1-GP  [C402H22]  160.81 114.57 180 top
PC8519  SC10U25V5KX-L-GP  [C805H56]  167.07 101.58 180 top
PC8520  SC4D7U25V5KX-L2-GP  [C805H58]  165.26 101.58 0 bottom
PC8521  SCD1U25V2KX-GP  [C402H22]  168.37 101.44 180 top
PC8522  SCD022U25V2KX-DLGP  [C402H22]  159.98 114.4 0 bottom
PC8523  SCD1U25V2KX-GP  [C402H22]  160.41 115.66 270 bottom
PC8524  SC330P50V2KX-3GP  [C402H22]  162.51 111.86 0 top
PC8525  SCD1U25V2KX-GP  [C402H22]  161.1 117.31 270 bottom
PC8526  SC4D7U25V5KX-L2-GP  [C805H58]  167.92 118.98 180 top
PC8527  SC4D7U25V5KX-L2-GP  [C805H58]  168.23 119 270 bottom
PC8528  SC10U25V5KX-L-GP  [C805H56]  166.9 114.21 180 bottom
PC8529  SC10U25V5KX-L-GP  [C805H56]  166.9 114.21 0 top
PC8530  SCD1U25V2KX-GP  [C402H22]  168.2 114.08 0 top
PC8531  SC10U25V5KX-L-GP  [C805H56]  167.07 101.58 0 bottom
PC8532  SC4D7U25V5KX-L2-GP  [C805H58]  165.25 101.57 180 top
PC8533  SC330P50V2KX-3GP  [C402H22]  173.76 107.04 270 top
PC8534  SC22U6D3V3MX-1-GP  [C603H40]  168.23 120.55 270 bottom
PC8535  SC22U6D3V3MX-1-GP  [C603H40]  168.18 123.67 90 top
PC8601  SCD1U16V2KX-3GP  [C402H22]  143.5 142.16 180 bottom
PC8602  SCD47U25V3KX-1GP  [C603H36]  148.47 138.56 0 bottom
PC8603  SCD1U16V2KX-3GP  [C402H22]  142.42 140.86 270 bottom
PC8604  SC22U6D3V3MX-1-DL-GP  [C603H40]  147.04 146.82 180 top
PC8605  SC22U6D3V3MX-1-DL-GP  [C603H40]  145.21 146.82 180 top
PC8607  SCD1U16V2KX-3GP  [C402H22]  142.82 149.72 180 bottom
PC8612  SCD22U10V2KX-L1-GP  [C402H22]  142.15 146.12 270 top
PC8621  SC10U6D3V3MX-GP  [C603H38]  136.51 152.68 0 bottom
PC8622  SC10U6D3V3MX-GP  [C603H38]  137.79 152.68 0 bottom
PC8623  SC1U10V2KX-1GP  [C402H22]  138.84 152.68 0 bottom
PC8624  SC22P50V2JN-4GP  [C402H22]  140.16 148.39 90 bottom
PC8625  SC22U6D3V3MX-1-GP  [C603H40]  146.67 149.48 90 bottom
PC8626  SC22U6D3V3MX-1-GP  [C603H40]  146.67 148.21 90 bottom
PC8634  SC1U10V2KX-1GP  [C402H22]  143.45 139.04 90 top
PC8635  SCD1U25V2KX-1-DL-GP  [C402H22]  142.58 138.18 270 top
PC8636  SCD1U16V2KX-3GP  [C402H22]  148.57 139.88 0 top
PC8651  SCD1U25V2KX-GP  [C402H22]  193.07 170.66 270 bottom
PC8652  SC10U25V5KX-L-GP  [C805H56]  192.95 172.02 270 bottom
PC8654  SC2D2U10V3KX-L-GP  [C603H36]  197.44 163.88 270 bottom
PC8655  SC1U10V2KX-1GP  [C402H22]  197.62 164.92 270 bottom
PC8656  SCD1U25V2KX-GP  [C402H22]  192.29 163.71 270 bottom
PC8657  SC22U6D3V3MX-1-DL-GP  [C603H40]  191.12 150.95 0 top
PC8658  SC22U6D3V3MX-1-DL-GP  [C603H40]  192.94 150.95 0 top
PC8659  SC22U6D3V3MX-1-DL-GP  [C603H40]  192.78 151.08 180 bottom
PC8660  SC22U6D3V3MX-1-DL-GP  [C603H40]  194.61 151.08 180 bottom
PC8661  SC22U6D3V3MX-1-DL-GP  [C603H40]  190.94 151.08 180 bottom
PC8662  SC470P50V2KX-L-GP  [C402H22]  197.74 166.79 90 bottom
PD4301  P6SMBJ24A-H-GP  [DO214AAAKH97]  77.8 167.13 90 bottom
PD4302  LBAV99LT1G-1-GP  [SOT23-2D4-312H44]  64.07 169.62 90 bottom
PD4303  PESD24VS2UT-GP  [SOT-23-10H44]  63.96 171.71 180 top
PD4304  SMF18A-GP  [SOD123AK-2H43]  153.58 176.07 90 bottom
PD4404  RB551V30-GP  [SOD323AKH38]  123.71 173.79 90 top
PD4410  BAT54C-12-GP  [SOT-23-9H44]  136.18 171.68 0 top
PD8501  RB551VM-30TE-17-GP  [SOD323-2513AKH36]  151.7 111.13 270 top
PG4407  GAP-CLOSE-PWR-3-GP  [GAP-CLOSE-PWR-3]  123.5 165.86 270 top
PG4426  GAP-CLOSE-PWR-3-GP  [GAP-CLOSE-PWR-3]  141.31 170.97 0 bottom
PG4428  GAP-CLOSE-PWR-3-GP  [GAP-CLOSE-PWR-3]  141.31 169.19 0 bottom
PG4429  GAP-CLOSE-PWR-3-GP  [GAP-CLOSE-PWR-3]  121.77 165.86 270 top
PG4517  -  [GAP-CLOSE-PWR]  41.86 46.81 270 bottom
PG4518  -  [GAP-CLOSE-PWR]  58.11 72 90 top
PG4519  -  [GAP-CLOSE-PWR]  56.5 52.53 180 bottom
PG4520  -  [GAP-CLOSE-PWR]  57.35 72 90 top
PG4521  -  [GAP-CLOSE-PWR]  40.08 71.84 90 top
PG4522  -  [GAP-CLOSE-PWR]  42.62 46.81 270 bottom
PG4523  -  [GAP-CLOSE-PWR]  52.4 47.09 90 bottom
PG4524  -  [GAP-CLOSE-PWR]  37.79 71.84 90 top
PG4525  -  [GAP-CLOSE-PWR]  38.55 71.84 90 top
PG4526  -  [GAP-CLOSE-PWR]  40.33 46.81 270 bottom
PG4527  -  [GAP-CLOSE-PWR]  56.5 53.29 180 bottom
PG4528  -  [GAP-CLOSE-PWR]  39.57 46.81 270 bottom
PG4529  -  [GAP-CLOSE-PWR]  41.1 46.81 270 bottom
PG4531  -  [GAP-CLOSE-PWR]  39.31 71.84 90 top
PG4532  GAP-CLOSE-PWR-3-GP  [GAP-CLOSE-PWR-3]  51.43 51.58 180 bottom
PG4533  -  [GAP-CLOSE-PWR]  56.5 51.76 180 bottom
PG4534  -  [GAP-CLOSE-PWR]  58.87 72 90 top
PG4535  GAP-CLOSE-PWR-3-GP  [GAP-CLOSE-PWR-3]  39.06 51.79 180 bottom
PG4536  -  [GAP-CLOSE-PWR]  59.63 72 90 top
PG4537  -  [GAP-CLOSE-PWR]  56.5 51 180 bottom
PG4538  -  [GAP-CLOSE-PWR]  56.5 50.24 180 bottom
PG4540  -  [GAP-CLOSE-PWR]  54.69 47.09 90 bottom
PG4541  -  [GAP-CLOSE-PWR]  53.17 47.09 90 bottom
PG4542  -  [GAP-CLOSE-PWR]  60.4 72 90 top
PG4543  -  [GAP-CLOSE-PWR]  56.59 72 90 top
PG4544  -  [GAP-CLOSE-PWR]  53.93 47.09 90 bottom
PG4545  -  [GAP-CLOSE-PWR]  51.64 47.09 90 bottom
PG4701  GAP-CLOSE-PWR-3-GP  [GAP-CLOSE-PWR-3]  102.15 129.64 270 top
PG4702  GAP-CLOSE-PWR-3-GP  [GAP-CLOSE-PWR-3]  101.21 129.64 270 top
PG4703  GAP-CLOSE-PWR-3-GP  [GAP-CLOSE-PWR-3]  100.27 129.64 270 top
PG4704  GAP-CLOSE-PWR-3-GP  [GAP-CLOSE-PWR-3]  99.33 129.64 270 top
PG4705  GAP-CLOSE-PWR-3-GP  [GAP-CLOSE-PWR-3]  102.32 129.63 270 bottom
PG4706  GAP-CLOSE-PWR-3-GP  [GAP-CLOSE-PWR-3]  103.26 129.63 270 bottom
PG4707  GAP-CLOSE-PWR-3-GP  [GAP-CLOSE-PWR-3]  103.66 119.23 90 bottom
PG4708  GAP-CLOSE-PWR-3-GP  [GAP-CLOSE-PWR-3]  103.66 117.2 270 bottom
PG4802  GAP-CLOSE-PWR-3-GP  [GAP-CLOSE-PWR-3]  117.88 129.28 90 bottom
PG4803  GAP-CLOSE-PWR-3-GP  [GAP-CLOSE-PWR-3]  118.82 129.28 90 bottom
PG4804  GAP-CLOSE-PWR-3-GP  [GAP-CLOSE-PWR-3]  120.7 129.28 90 bottom
PG4805  GAP-CLOSE-PWR-3-GP  [GAP-CLOSE-PWR-3]  121.64 129.28 90 bottom
PG4806  GAP-CLOSE-PWR-3-GP  [GAP-CLOSE-PWR-3]  119.76 129.28 90 bottom
PG4808  GAP-CLOSE-PWR-3-GP  [GAP-CLOSE-PWR-3]  122.94 119.13 270 bottom
PG4809  GAP-CLOSE-PWR-3-GP  [GAP-CLOSE-PWR-3]  122.94 116.97 90 bottom
PG4810  GAP-CLOSE-PWR-3-GP  [GAP-CLOSE-PWR-3]  111.69 129.41 90 bottom
PG4811  GAP-CLOSE-PWR-3-GP  [GAP-CLOSE-PWR-3]  110.75 129.41 90 bottom
PG4812  GAP-CLOSE-PWR-3-GP  [GAP-CLOSE-PWR-3]  109.81 129.41 90 bottom
PG4813  GAP-CLOSE-PWR-3-GP  [GAP-CLOSE-PWR-3]  113.14 119 270 bottom
PG4814  GAP-CLOSE-PWR-3-GP  [GAP-CLOSE-PWR-3]  108.87 129.41 90 bottom
PG4815  GAP-CLOSE-PWR-3-GP  [GAP-CLOSE-PWR-3]  113.14 116.97 90 bottom
PG4816  GAP-CLOSE-PWR-3-GP  [GAP-CLOSE-PWR-3]  112.62 129.42 90 bottom
PG5001  GAP-CLOSE-PWR-3-GP  [GAP-CLOSE-PWR-3]  135.87 116.95 270 bottom
PG5002  GAP-CLOSE-PWR-3-GP  [GAP-CLOSE-PWR-3]  133.38 127.55 90 bottom
PG5003  GAP-CLOSE-PWR-3-GP  [GAP-CLOSE-PWR-3]  132.4 127.55 90 bottom
PG5011  GAP-CLOSE-PWR-3-GP  [GAP-CLOSE-PWR-3]  135.87 119.06 90 bottom
PG5101  GAP-CLOSE-PWR-3-GP  [GAP-CLOSE-PWR-3]  58.48 31.75 90 top
PG5113  GAP-CLOSE-PWR-3-GP  [GAP-CLOSE-PWR-3]  36.03 25.09 270 top
PG5114  GAP-CLOSE-PWR-3-GP  [GAP-CLOSE-PWR-3]  35.27 25.09 270 top
PG5115  GAP-CLOSE-PWR-3-GP  [GAP-CLOSE-PWR-3]  36.94 27.94 270 top
PG5116  GAP-CLOSE-PWR-3-GP  [GAP-CLOSE-PWR-3]  36.18 27.94 270 top
PG5117  GAP-CLOSE-PWR-3-GP  [GAP-CLOSE-PWR-3]  51.09 17.14 90 bottom
PG5118  GAP-CLOSE-PWR-3-GP  [GAP-CLOSE-PWR-3]  50.33 17.14 90 bottom
PG5119  GAP-CLOSE-PWR-3-GP  [GAP-CLOSE-PWR-3]  58.35 38.38 0 top
PG5120  GAP-CLOSE-PWR-3-GP  [GAP-CLOSE-PWR-3]  58.34 37.44 0 top
